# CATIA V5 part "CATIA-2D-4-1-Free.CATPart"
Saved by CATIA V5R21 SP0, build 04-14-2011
Part number: CATIA-2D-4-1-Free
Bounding box of the stored display mesh (mm): x -6 to 21, y -1 to 1, z -5.988 to 47
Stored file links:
  C:\Users\Rasoul Mohammadi\Desktop\CATIA-Free\2D\CATIA-2D-4-1-Free.CATPart
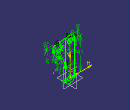
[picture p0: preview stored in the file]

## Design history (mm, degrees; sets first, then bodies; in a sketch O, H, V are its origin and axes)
Body1 (main body)
  Sketch1 on zx-plane, origin (0, 0, 0), H (-1, 0, 0), V (0, 0, 1)
    construction line L1 (0, 0) -> (0, 41)
    line L2 (-6, 0) -> (-6, 46.4024)
    line L3 (6, 41) -> (6, 0)
    arc A1 centre (0, 41) radius 6 from (-0.6272, 46.9671) to (6, 41) cw
    arc A2 centre (0, 0) radius 6 from (6, 0) to (-6, 0) cw
    point P3 (-6, 46.4024)
    construction line L4 (0, 0) -> (-14.0228, 38.5274)
    line L5 (-0.6272, 46.9671) -> (-13.413, 45.6233)
    axis line L6 (-0.6272, 46.9671) -> (-14.0694, 46.9671)
    line L7 (-21, 44.8259) -> (-21, 40)
    arc A3 centre (-14.0228, 38.5274) radius 3 from (-16.8419, 37.5013) to (-11.2037, 39.5535) ccw
    line L8 (-11.2037, 39.5535) -> (-13.413, 45.6233)
    line L9 (-19.5628, 44.9769) -> (-16.8419, 37.5013)
    arc A4 centre (-9, 40) radius 12 from (-21, 40) to (-14.3333, 29.2503) ccw
    point P14 (-9, 40)
    point P16 (-19.5628, 44.9769)
    line L10 (-19.5628, 44.9769) -> (-21, 44.8259)
    point P17 (-6, 7.7135)
    arc A5 centre (-21, 15.8132) radius 15 from (-14.3333, 29.2503) to (-6, 15.8132) cw
    point P19 (-6, 15.8132)
    circle A6 centre (0, 41) radius 3
    circle A7 centre (0, 0) radius 3
    distance L1 L2 = 6
    length L1 = 41
    angle L4 L1 = 20
    length L4 = 41
    angle L6 L5 = 6
    radius A3 = 3
    distance L1 P14 = 9
    radius A4 = 12
    distance P14 A1 V = 7
    radius A5 = 15
    radius A6 = 3
    radius A7 = 3
    radius A1 = 6
    vertical: L1 V, L7 V
    tangency: A2 L2, A1 L3, A2 L3, L8 A3, L9 A3, L5 A1, A4 L7, A5 L2, A5 A4
    horizontal: L6 H
    parallelism: L4 L8, L4 L9
    coincidence: L5 P16, L5 L10, P17 L9, P17 L2, P19 L2, P3 L5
